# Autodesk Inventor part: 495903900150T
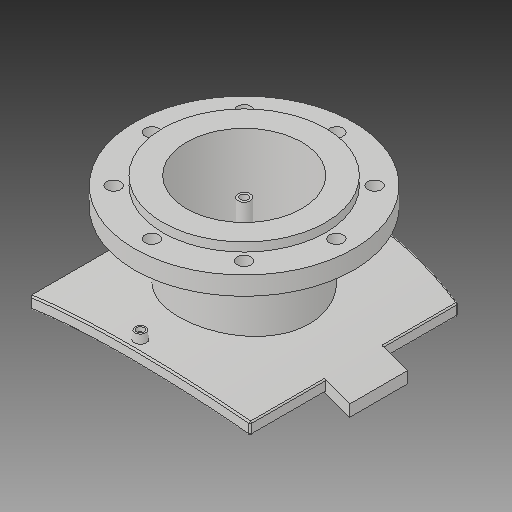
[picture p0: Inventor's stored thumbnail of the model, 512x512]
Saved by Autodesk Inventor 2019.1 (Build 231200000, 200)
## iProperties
Created: 2017-10
Part Number: 495903900150T
Material: Generic
Description: PLASSON FLANGED BRANCH SADDLE 900x150
Document SubType Name: Modeling
Designer: KIM
Mass: 2339.99 g
Surface Area: 3251.55 cm^2
Volume: 2339.99 cm^3
Density: 1 g/cm^3
Appearance: Default
Author: KIM
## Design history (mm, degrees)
derived "495904_495903.ipt"
feature "Solid1::495904_495903.ipt"
feature "Solid2::495904_495903.ipt"
tag "TaggingFeature1"
body "Solid1"
other parameters: "d1" = 15, "d2" = 286.2, "d4" = 0, "d6" = 75, "d7" = 0, "d12" = 475.6, "d13" = 14, "d14" = 135, "d16" = 5 deg, "d18" = 4, "d19" = 14, "d20" = 0, "d21" = 3, "d22" = 0, "d23" = 597, "d36" = 135, "d38" = 0, "d39" = 2, "d42" = 212, "d43" = 285, "d44" = 105.6, "d46" = 169.6, "d47" = 16, "d48" = 10.4, "d49" = 92.4, "d51" = 918, "d53" = 0, "d54" = 18, "d57" = 0, "d59" = 360 deg, "d61" = 24, "d63" = 0, "d66" = 132, "d67" = 15, "d68" = 66, "d70" = 0, "d71" = 2, "d72" = 318, "d_1" = 212, "B_" = 318, "H_" = 132, "x_" = 15, "D_" = 16, "D_1" = 285, "t_" = 24, "s_" = 18
